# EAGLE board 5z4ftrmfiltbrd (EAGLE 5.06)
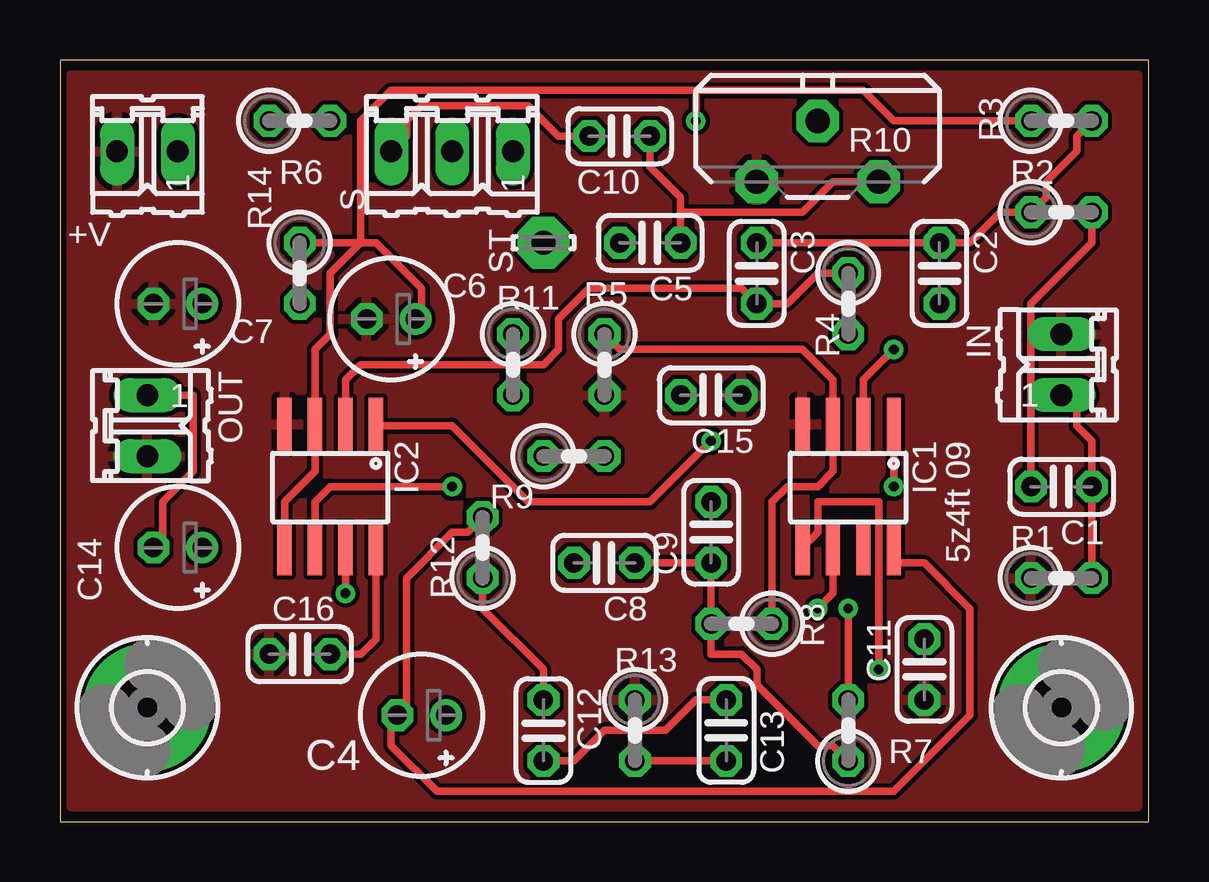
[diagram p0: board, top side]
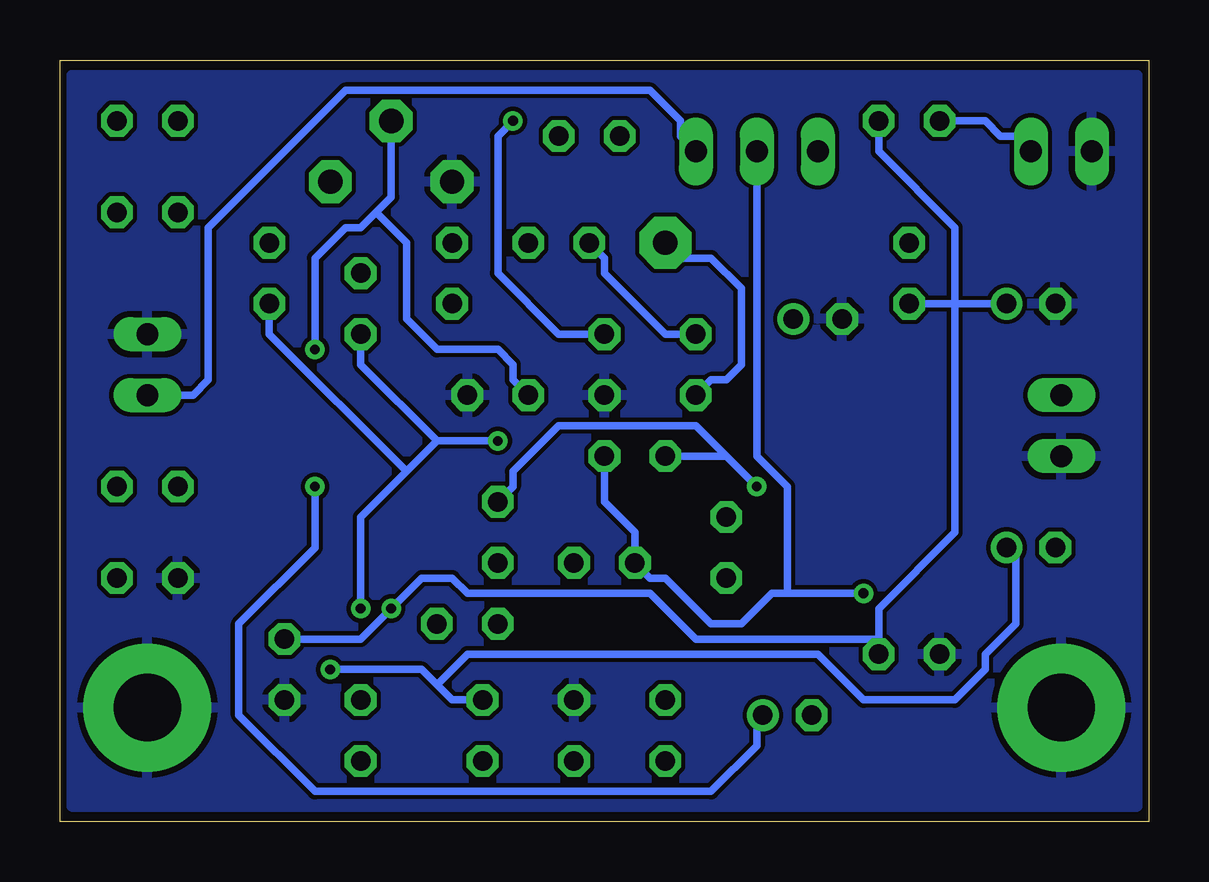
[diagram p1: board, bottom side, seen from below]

Size 45.39 x 31.74 mm. Coordinates in mm from the lower left corner, seen from the top.
Outline: 45.39,31.74 0,31.74 0,0 45.39,0 45.39,31.74
Copper layers (1*16): Top 0.0356mm / dielectric 1.5011mm / Bottom 0.0356mm
Design rules "SilverCircuits *": minimum track width 12mil, minimum drill 16mil, track to track 7mil, track to pad 7mil, pad to pad 7mil, via to via 7mil, smd to smd 0mil, copper to edge 10mil, drill to drill 8mil, minimum pad ring 10mil, minimum via ring 8mil, stop-mask expansion 4mil, vias tented up to drill 24mil, thermal gap 10mil

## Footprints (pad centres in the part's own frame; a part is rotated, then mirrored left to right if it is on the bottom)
02P = drill 0.914 long: 1 -1.27,0; 2 1.27,0
C025-024X044 = drill 0.813 octagon: 1 -1.27,0; 2 1.27,0
E2-5 = drill 0.813 pad 1.27 round: + -1.016,0 | drill 0.813 pad 1.27 octagon: - 1.016,0
2,8-PAD = drill 2.8 pad 5.334 round: B2,8 0,0
SO08 = smd 0.6 x 2.2: 1 -1.905,-2.6; 2 -0.635,-2.6; 3 0.635,-2.6; 4 1.905,-2.6; 5 1.905,2.6; 6 0.635,2.6; 7 -0.635,2.6; 8 -1.905,2.6
0207/2V = drill 0.813 octagon: 1 -1.27,0; 2 1.27,0
PT-10S = drill 1.016 pad 1.778 octagon: 1 -2.54,-1.27; 2 2.54,-1.27; 3 0,1.27
03P = drill 0.914 long: 1 -2.54,0; 2 0,0; 3 2.54,0
LSP10 = drill 1.016 pad 2.159 octagon: MP 0,0

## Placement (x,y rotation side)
+V  [02P]  3.65,27.94 180 top
C1  0.1uF  [C025-024X044]  41.74,13.96 180 top
C2  0.01uF  [C025-024X044]  36.66,22.86 270 top
C3  0.01uF  [C025-024X044]  29.05,22.86 270 top
C4  10uF/16V  [E2-5]  15.08,4.44 180 top
C5  0.1uF  [C025-024X044]  24.6,24.12 180 top
C6  10uF/16V  [E2-5]  13.81,20.95 180 top
C7  47uF/16V  [E2-5]  4.92,21.59 180 top
C8  0.01uF  [C025-024X044]  22.7,10.79 180 top
C9  0.01uF  [C025-024X044]  27.14,12.06 90 top
C10  0.1uF  [C025-024X044]  23.33,28.57 180 top
C11  0.01uF  [C025-024X044]  36.03,6.34 90 top
C12  0.022uF  [C025-024X044]  20.16,3.81 270 top
C13  0.1uF  [C025-024X044]  27.78,3.81 90 top
C14  47uF/16V  [E2-5]  4.92,11.42 180 top
C15  0.01uF  [C025-024X044]  27.14,17.78 180 top
C16  0.01uF  [C025-024X044]  10,6.98 0 top
H1  [2,8-PAD]  41.74,4.76 180 top
H2  [2,8-PAD]  3.65,4.76 180 top
IC1  LM386M-1  [SO08]  32.86,13.96 180 top
IC2  TL072D  [SO08]  11.27,13.96 180 top
IN  [02P]  41.74,19.05 90 top
OUT  [02P]  3.65,16.51 270 top
R1  1K  [0207/2V]  41.74,10.15 0 top
R2  82K  [0207/2V]  41.74,25.39 0 top
R3  3K  [0207/2V]  41.74,29.21 0 top
R4  160K  [0207/2V]  32.86,21.59 270 top
R5  10K  [0207/2V]  22.7,19.05 270 top
R6  10  [0207/2V]  10,29.21 0 top
R7  82K  [0207/2V]  32.86,3.81 90 top
R8  3K  [0207/2V]  28.41,8.25 180 top
R9  160K  [0207/2V]  21.43,15.23 0 top
R10  50K  [PT-10S]  31.59,27.94 0 top
R11  13.3K  [0207/2V]  18.89,19.05 270 top
R12  10K  [0207/2V]  17.62,11.42 90 top
R13  10  [0207/2V]  23.96,3.81 270 top
R14  10K  [0207/2V]  10,22.86 270 top
S  [03P]  16.35,27.94 180 top
ST  LSP10  [LSP10]  20.16,24.12 0 top

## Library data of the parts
+V IN OUT S = con-amp-quick
C1-C16 R1-R9 R11-R14 = rcl
H1 H2 = holes
IC1 IC2 = linear
R10 = discrete
ST = solpad

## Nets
GND: +V.2 C6.- C7.- C11.1 C15.1 C16.1 H1.B2,8 H2.B2,8 IC1.4 IC2.4 IN.2 OUT.2 R1.1 R5.2 R10.1 R13.1
N$1: C2.1 C3.1 R2.1 R3.2
N$2: C1.1 IN.1 R1.2 S.1
N$3: C1.2 R2.2
N$4: C4.+ IC1.1
N$5: C3.2 IC2.2 R4.1
N$6: C8.1 C9.1 R7.1 R8.2
N$7: C8.2 IC2.7 R9.2 S.2
N$8: C4.- IC1.8 R12.2
N$9: C9.2 IC2.6 R9.1
N$10: C10.2 S.3
N$11: C7.+ C11.2 C16.2 IC1.6 IC2.8 R6.2 R14.2
N$12: C5.1 C10.1 R10.2
N$13: C12.1 R12.1
N$14: C12.2 C13.2 C14.+ IC1.5
N$15: C5.2 R11.1
N$16: C13.1 R13.2
N$17: C15.2 IC1.2 R10.3
N$18: C14.- OUT.1
N$19: R11.2 ST.MP
N$20: C6.+ IC1.3 IC2.3 IC2.5 R3.1 R5.1 R8.1 R14.1
N$21: C2.2 IC2.1 R4.2 R7.2
V+: +V.1 R6.1

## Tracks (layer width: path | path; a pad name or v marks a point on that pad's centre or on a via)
GND
  pour Bottom: 44.92,0.63 0.47,0.63 0.47,31.11 44.92,31.11
  pour Top: 44.92,0.63 0.47,0.63 0.47,31.11 44.92,31.11
N$1
  Top 0.305: C3.1 C2.1 37.94,24.12 39.2,25.39 R2.1 41.11,26.03 41.11,26.67 42.38,27.94 42.38,28.57 R3.2
N$2
  Top 0.305: R1.2 C1.1 43.02,15.87 42.38,16.51 42.38,17.14 IN.1
  Bottom 0.305: S.1 19.52,28.57 19.52,29.21 20.79,30.48 33.49,30.48 39.2,24.76 39.2,18.41 39.84,17.78 IN.1
N$3
  Top 0.305: C1.2 40.48,21.59 43.02,24.12 R2.2
N$4  (via drill 0.41)
  Top 0.305: v34.76,13.96 34.76,16.51 IC1.1
  Bottom 0.305: v34.76,13.96 34.76,11.42 37.94,8.25 37.94,4.44 34.76,1.27 18.25,1.27 16.35,3.17 16.35,4.44 C4.+
N$5
  Top 0.305: IC2.2 11.9,17.14 11.9,18.41 12.54,19.05 20.16,19.05 20.79,19.68 20.79,20.95 22.06,22.22 28.41,22.22 C3.2 30.32,21.59 31.59,22.86 R4.1
N$6
  Top 0.305: C8.1 C9.1 R8.2 27.14,6.98 28.41,6.98 29.05,6.34 29.05,5.71 31.59,3.17 32.22,3.17 R7.1
N$7  (via drill 0.41)
  Top 0.305: v11.9,9.52 11.9,10.79 IC2.7
  Bottom 0.305: 15.08,9.52 15.71,9.52 16.98,8.25 18.25,8.25 20.16,10.15 20.79,10.15 C8.2 21.43,12.06 22.7,13.33 R9.2 | v11.9,9.52 15.08,9.52 | S.2 16.35,15.23 15.08,13.96 15.08,9.52
N$8
  Top 0.305: IC1.8 34.76,10.79 36.03,10.79 37.94,8.88 37.94,4.44 34.76,1.27 15.71,1.27 13.81,3.17 13.81,4.44 C4.- 14.44,4.44 14.44,10.15 16.35,12.06 16.98,12.06 R12.2
N$9  (via drill 0.41)
  Top 0.305: v16.35,13.96 11.27,13.96 10.63,13.33 10.63,11.42 IC2.6
  Bottom 0.305: v16.35,13.96 17.62,15.23 | 17.62,15.23 R9.1 | C9.2 26.51,13.96 26.51,14.6 24.6,16.51 18.89,16.51 17.62,15.23
N$10
  Top 0.305: C10.2 20.79,28.57 19.52,29.84 15.08,29.84 14.44,29.21 14.44,28.57 S.3
N$11  (via drill 0.41)
  Top 0.305: v31.59,8.88 32.22,9.52 32.22,10.79 IC1.6 | C16.2 12.54,6.98 13.17,7.62 13.17,10.79 IC2.8
  Bottom 0.305: C11.2 32.86,7.62 v31.59,8.88 30.32,10.15 29.05,10.15 28.41,9.52 20.79,9.52 18.89,7.62 11.27,7.62 | 8.09,21.59 R14.2 | 8.09,21.59 6.18,21.59 C7.+ | R6.2 11.27,27.94 8.09,24.76 8.09,21.59 | 11.27,7.62 11.27,8.88 8.09,12.06 8.09,21.59 | 11.27,7.62 C16.2 11.27,7.62
N$12
  Top 0.305: 25.87,25.39 25.87,26.03 24.6,27.3 C10.1 | C5.1 25.87,25.39 | R10.2 32.22,26.67 30.95,25.39 25.87,25.39
N$13
  Top 0.305: C12.1 20.16,6.34 17.62,8.88 R12.1
N$14  (via drill 0.41)
  Top 0.305: v34.12,6.34 34.12,13.33 31.59,13.33 31.59,12.06 30.95,11.42 IC1.5 | C12.2 21.43,2.54 22.7,3.81 25.23,3.81 26.51,5.08 C13.2
  Bottom 0.305: v34.12,6.34 30.32,6.34 29.68,5.71 | 29.68,5.71 29.05,5.08 C13.2 | 29.68,5.71 28.41,6.98 13.81,6.98 11.9,5.08 8.09,5.08 6.82,6.34 6.82,6.98 5.55,8.25 5.55,11.42 C14.+
N$15
  Bottom 0.305: R11.1 20.16,20.32 22.7,22.86 22.7,23.49 C5.2
N$16
  Top 0.305: R13.2 C13.1
N$17  (via drill 0.41)
  Top 0.305: v34.76,19.68 33.49,18.41 33.49,17.14 IC1.2
  Bottom 0.305: v34.76,19.68 34.76,23.49 33.49,24.76 32.86,24.76 32.22,25.39 | 32.22,25.39 31.59,26.03 R10.3 | C15.2 26.51,18.41 26.51,19.05 27.14,19.68 29.68,19.68 30.95,20.95 30.95,24.12 32.22,25.39
N$18
  Top 0.305: OUT.1 5.55,17.78 5.55,14.6 4.28,13.33 4.28,11.42 C14.-
N$19
  Bottom 0.305: R11.2 18.25,18.41 17.62,18.41 16.98,19.05 16.98,22.22 18.25,23.49 19.52,23.49 ST.MP
N$20  (via drill 0.41)
  Top 0.305: R5.1 23.33,19.68 30.95,19.68 32.22,18.41 32.22,17.14 IC1.3 32.22,16.51 32.22,14.6 31.59,13.96 30.32,13.96 29.68,13.33 R8.1 | IC2.5 9.36,11.42 9.36,13.33 10.63,14.6 10.63,16.51 IC2.3 10.63,17.14 10.63,19.68 11.27,20.32 11.27,22.86 12.54,24.12 | 12.54,24.12 13.17,24.12 15.08,22.22 15.08,20.95 C6.+ | 12.54,24.12 R14.1 | R3.1 34.76,29.21 33.49,30.48 26.51,30.48 | 26.51,30.48 13.81,30.48 12.54,29.21 12.54,24.12 | 26.51,30.48 v26.51,29.21
  Bottom 0.305: R5.1 24.6,20.32 27.14,22.86 27.14,28.57 v26.51,29.21
N$21  (via drill 0.41)
  Top 0.305: v27.14,15.87 24.6,13.33 19.52,13.33 16.35,16.51 13.17,16.51 IC2.1 | v32.86,8.88 R7.2
  Bottom 0.305: v27.14,15.87 29.68,15.87 | 29.68,15.87 32.86,19.05 R4.2 | v32.86,8.88 32.86,12.69 30.95,14.6 | 29.68,15.87 30.95,14.6 | C2.2 36.66,20.32 30.95,14.6
V+
  Bottom 0.305: R6.1 6.82,29.21 6.18,28.57 5.55,28.57 +V.1

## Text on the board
tPlace: 5z4ft 09
_tsilk: R10 | R3 | 1 | R6 | 1 | R2 | S | C10 | +V | R14 | C3 | C2 | ST | C5 | C6 | R11 | R5 | R4 | C7 | OUT | IN | 1 | 1 | IC2 | C15 | IC1 | R9 | C1 | C14 | 5z4ft 09 | R1 | C9 | R12 | C8 | R8 | C16 | C12 | R13 | C11 | C4 | C13 | R7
